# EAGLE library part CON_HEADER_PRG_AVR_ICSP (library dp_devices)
2x3 AVR ICSP programming header
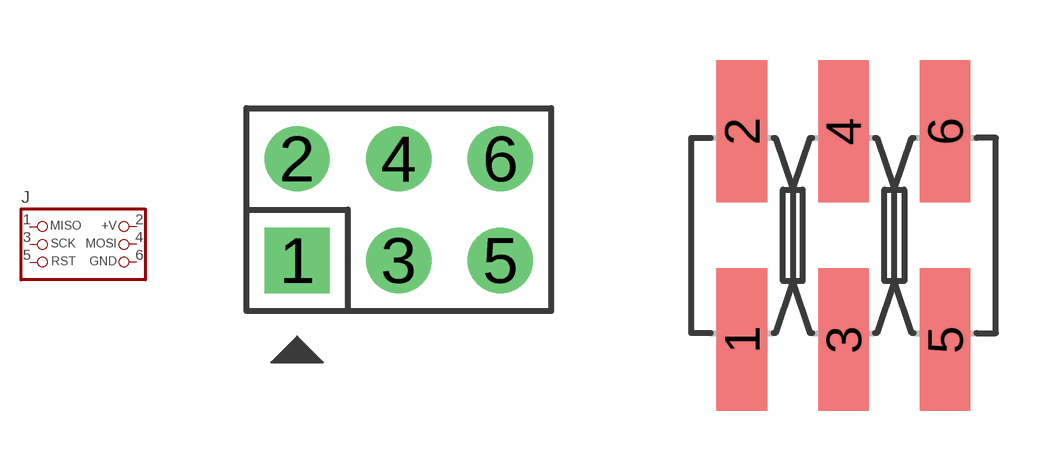
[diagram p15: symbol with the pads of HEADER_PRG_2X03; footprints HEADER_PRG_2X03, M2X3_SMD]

Designator prefix J

## CON_HEADER_PRG_AVR_ICSP-PTH  [HEADER_PRG_2X03]
1  MISO  pas
2  +V  pas
3  SCK  pas
4  MOSI  pas
5  RST  pas
6  GND  pas

## CON_HEADER_PRG_AVR_ICSP-SMD  [M2X3_SMD]
Pads as for HEADER_PRG_2X03

## Footprint HEADER_PRG_2X03 (pad centres in mm)
drill 1.02 pad 1.632 square: 1 -2.54,-1.27
drill 1.02 pad 1.632 round: 2 -2.54,1.27; 3 0,-1.27; 4 0,1.27; 5 2.54,-1.27; 6 2.54,1.27

## Footprint M2X3_SMD (pad centres in mm)
2x03 Straight male header SMD Mfr no:5-146134-2 5-146134-2
smd 1.27 x 3.56: 1 -2.54,-2.605; 2 -2.54,2.605; 3 0,-2.605; 4 0,2.605; 5 2.54,-2.605; 6 2.54,2.605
